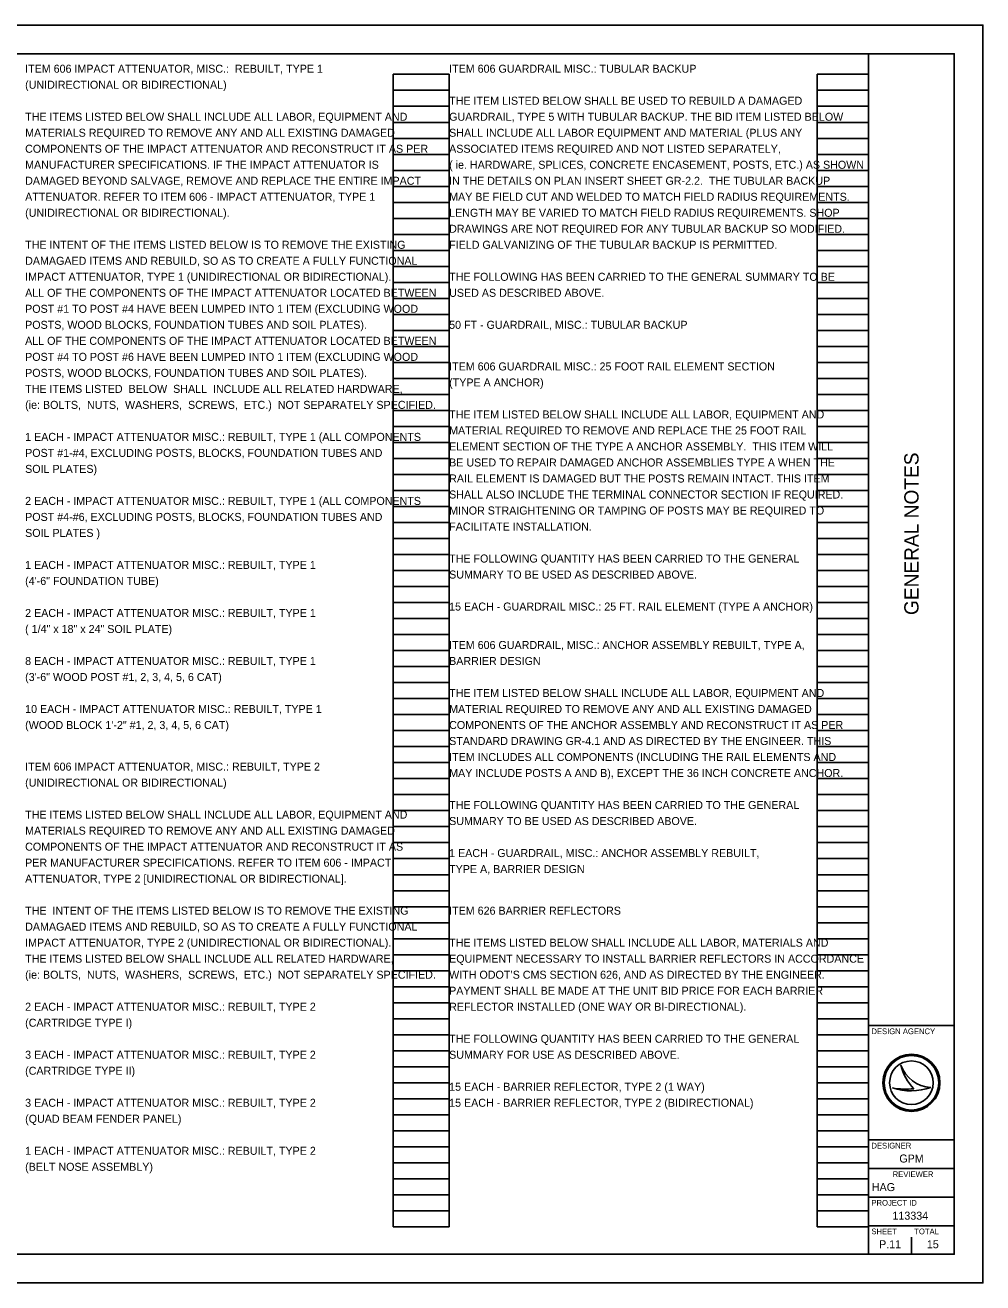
# Model space of a CAD drawing. Extents: x 0 to 34, y 0 to 22.
# Drawn here: x 17.24 to 34, y 0 to 22 of the extents above; entities that cross this region are included whole.
import ezdxf

# ---------------------------------------------------------------- set-up
doc = ezdxf.new("R2010")
doc.units = 0
for name, color, linetype in [('SH_Border', 7, 'Continuous'), ('SH_Cut_Line', 7, 'Continuous'), ('SH_Data', 7, 'Continuous'), ('SH_Text', 7, 'Continuous')]:
    doc.layers.add(name, color=color, linetype=linetype)

msp = doc.modelspace()

# ---------------------------------------------------------------- linework, layer by layer
at = {"layer": 'SH_Border'}
for p, q in [((32, 0.5), (32, 21.5)), ((32, 4.5), (33.5, 4.5)), ((32, 2.5), (33.5, 2.5)), ((32, 2), (33.5, 2)), ((32, 1.5), (33.5, 1.5)), ((32, 1), (33.5, 1))]:
    msp.add_line(p, q, dxfattribs=at)
msp.add_lwpolyline([(1.5, 21.5), (33.5, 21.5), (33.5, 0.5), (1.5, 0.5)], close=True, dxfattribs=at)
at = {"layer": 'SH_Cut_Line'}
msp.add_lwpolyline([(0, 0), (34, 0), (34, 22), (0, 22)], close=True, dxfattribs=at)
at = {"layer": 'SH_Data'}
for p, q in [((23.68, 0.98), (23.68, 21.14)), ((23.68, 21.14), (24.66, 21.14)), ((24.66, 0.98), (24.66, 21.14)), ((31.1, 0.98), (31.1, 21.14)), ((31.1, 21.14), (32, 21.14)), ((32, 0.98), (32, 21.14)), ((23.68, 20.86), (24.66, 20.86)), ((31.1, 20.86), (32, 20.86)), ((23.68, 20.58), (24.66, 20.58)), ((31.1, 20.58), (32, 20.58)), ((23.68, 20.3), (24.66, 20.3)), ((31.1, 20.3), (32, 20.3)), ((23.68, 20.02), (24.66, 20.02)), ((31.1, 20.02), (32, 20.02)), ((23.68, 19.74), (24.66, 19.74)), ((31.1, 19.74), (32, 19.74)), ((23.68, 19.46), (24.66, 19.46)), ((31.1, 19.46), (32, 19.46)), ((23.68, 19.18), (24.66, 19.18)), ((31.1, 19.18), (32, 19.18)), ((23.68, 18.9), (24.66, 18.9)), ((31.1, 18.9), (32, 18.9)), ((23.68, 18.62), (24.66, 18.62)), ((31.1, 18.62), (32, 18.62)), ((23.68, 18.34), (24.66, 18.34)), ((31.1, 18.34), (32, 18.34)), ((23.68, 18.06), (24.66, 18.06)), ((31.1, 18.06), (32, 18.06)), ((23.68, 17.78), (24.66, 17.78)), ((31.1, 17.78), (32, 17.78)), ((23.68, 17.5), (24.66, 17.5)), ((31.1, 17.5), (32, 17.5)), ((23.68, 17.22), (24.66, 17.22)), ((31.1, 17.22), (32, 17.22)), ((23.68, 16.94), (24.66, 16.94)), ((31.1, 16.94), (32, 16.94)), ((23.68, 16.66), (24.66, 16.66)), ((31.1, 16.66), (32, 16.66)), ((23.68, 16.38), (24.66, 16.38)), ((31.1, 16.38), (32, 16.38)), ((23.68, 16.1), (24.66, 16.1)), ((31.1, 16.1), (32, 16.1)), ((23.68, 15.82), (24.66, 15.82)), ((31.1, 15.82), (32, 15.82)), ((23.68, 15.54), (24.66, 15.54)), ((31.1, 15.54), (32, 15.54)), ((23.68, 15.26), (24.66, 15.26)), ((31.1, 15.26), (32, 15.26)), ((23.68, 14.98), (24.66, 14.98)), ((31.1, 14.98), (32, 14.98)), ((23.68, 14.7), (24.66, 14.7)), ((31.1, 14.7), (32, 14.7)), ((23.68, 14.42), (24.66, 14.42)), ((31.1, 14.42), (32, 14.42)), ((23.68, 14.14), (24.66, 14.14)), ((31.1, 14.14), (32, 14.14)), ((23.68, 13.86), (24.66, 13.86)), ((31.1, 13.86), (32, 13.86)), ((23.68, 13.58), (24.66, 13.58)), ((31.1, 13.58), (32, 13.58)), ((23.68, 13.3), (24.66, 13.3)), ((31.1, 13.3), (32, 13.3)), ((23.68, 13.02), (24.66, 13.02)), ((31.1, 13.02), (32, 13.02)), ((23.68, 12.74), (24.66, 12.74)), ((31.1, 12.74), (32, 12.74)), ((23.68, 12.46), (24.66, 12.46)), ((31.1, 12.46), (32, 12.46)), ((23.68, 12.18), (24.66, 12.18)), ((31.1, 12.18), (32, 12.18)), ((23.68, 11.9), (24.66, 11.9)), ((31.1, 11.9), (32, 11.9)), ((23.68, 11.62), (24.66, 11.62)), ((31.1, 11.62), (32, 11.62)), ((23.68, 11.34), (24.66, 11.34)), ((31.1, 11.34), (32, 11.34)), ((23.68, 11.06), (24.66, 11.06)), ((31.1, 11.06), (32, 11.06)), ((23.68, 10.78), (24.66, 10.78)), ((31.1, 10.78), (32, 10.78)), ((23.68, 10.5), (24.66, 10.5)), ((31.1, 10.5), (32, 10.5)), ((23.68, 10.22), (24.66, 10.22)), ((31.1, 10.22), (32, 10.22)), ((23.68, 9.94), (24.66, 9.94)), ((31.1, 9.94), (32, 9.94)), ((23.68, 9.66), (24.66, 9.66)), ((31.1, 9.66), (32, 9.66)), ((23.68, 9.38), (24.66, 9.38)), ((31.1, 9.38), (32, 9.38)), ((23.68, 9.1), (24.66, 9.1)), ((31.1, 9.1), (32, 9.1)), ((23.68, 8.82), (24.66, 8.82)), ((31.1, 8.82), (32, 8.82)), ((23.68, 8.54), (24.66, 8.54)), ((31.1, 8.54), (32, 8.54)), ((23.68, 8.26), (24.66, 8.26)), ((31.1, 8.26), (32, 8.26)), ((23.68, 7.98), (24.66, 7.98)), ((31.1, 7.98), (32, 7.98)), ((23.68, 7.7), (24.66, 7.7)), ((31.1, 7.7), (32, 7.7)), ((23.68, 7.42), (24.66, 7.42)), ((31.1, 7.42), (32, 7.42)), ((23.68, 7.14), (24.66, 7.14)), ((31.1, 7.14), (32, 7.14)), ((23.68, 6.86), (24.66, 6.86)), ((31.1, 6.86), (32, 6.86)), ((23.68, 6.58), (24.66, 6.58)), ((31.1, 6.58), (32, 6.58)), ((23.68, 6.3), (24.66, 6.3)), ((31.1, 6.3), (32, 6.3)), ((23.68, 6.02), (24.66, 6.02)), ((31.1, 6.02), (32, 6.02)), ((23.68, 5.74), (24.66, 5.74)), ((31.1, 5.74), (32, 5.74)), ((23.68, 5.46), (24.66, 5.46)), ((31.1, 5.46), (32, 5.46)), ((23.68, 5.18), (24.66, 5.18)), ((31.1, 5.18), (32, 5.18)), ((23.68, 4.9), (24.66, 4.9)), ((31.1, 4.9), (32, 4.9)), ((23.68, 4.62), (24.66, 4.62)), ((31.1, 4.62), (32, 4.62)), ((23.68, 4.34), (24.66, 4.34)), ((31.1, 4.34), (32, 4.34)), ((23.68, 4.06), (24.66, 4.06)), ((31.1, 4.06), (32, 4.06)), ((23.68, 3.78), (24.66, 3.78)), ((31.1, 3.78), (32, 3.78)), ((32.567, 3.81), (32.567, 3.81)), ((23.68, 3.5), (24.66, 3.5)), ((31.1, 3.5), (32, 3.5)), ((32.417, 3.41), (32.417, 3.41)), ((32.75, 3.5), (32.75, 3.5)), ((33.087, 3.419), (33.087, 3.419)), ((23.68, 3.22), (24.66, 3.22)), ((31.1, 3.22), (32, 3.22)), ((23.68, 2.94), (24.66, 2.94)), ((31.1, 2.94), (32, 2.94)), ((23.68, 2.66), (24.66, 2.66)), ((31.1, 2.66), (32, 2.66)), ((23.68, 2.38), (24.66, 2.38)), ((31.1, 2.38), (32, 2.38)), ((23.68, 2.1), (24.66, 2.1)), ((31.1, 2.1), (32, 2.1)), ((23.68, 1.82), (24.66, 1.82)), ((31.1, 1.82), (32, 1.82)), ((23.68, 1.54), (24.66, 1.54)), ((31.1, 1.54), (32, 1.54)), ((23.68, 1.26), (24.66, 1.26)), ((31.1, 1.26), (32, 1.26)), ((23.68, 0.98), (24.66, 0.98)), ((31.1, 0.98), (32, 0.98)), ((32.375, 0.675), (32.375, 0.675)), ((32.75, 0.5), (32.75, 0.8))]:
    msp.add_line(p, q, dxfattribs=at)
for radius in [0.5, 0.477, 0.477, 0.382]:
    msp.add_circle((32.75, 3.5), radius, dxfattribs=at)
for centre, radius, start, end in [((33.116, 3.998), 0.58, 198.9257, 198.9319), ((33.347, 3.97), 0.796, 191.6379, 191.6421), ((33.116, 3.998), 0.58, 198.9319, 267.1657), ((33.347, 3.97), 0.796, 191.6421, 226.0947), ((32.739, 4.37), 1.013, 251.4576, 290.0832), ((32.648, 4.654), 1.266, 259.4964, 259.4995), ((32.739, 4.37), 1.013, 251.4527, 251.4576), ((32.648, 4.654), 1.266, 259.4995, 276.6672)]:
    msp.add_arc(centre, radius, start, end, dxfattribs=at)

# ---------------------------------------------------------------- texts
msp.add_text('GENERAL NOTES', height=0.25, rotation=90, dxfattribs=at).set_placement((32.875, 11.682))
for s, height, p in [('DESIGN AGENCY', 0.1, (32.05, 4.35)), ('DESIGNER', 0.1, (32.05, 2.35)), ('GPM', 0.14, (32.538, 2.105)), ('REVIEWER', 0.1, (32.422, 1.85)), ('HAG', 0.14, (32.057, 1.605)), ('PROJECT ID', 0.1, (32.05, 1.35)), ('113334', 0.14, (32.418, 1.105)), ('SHEET', 0.1, (32.05, 0.85)), ('TOTAL', 0.1, (32.8, 0.85)), ('P.11', 0.14, (32.184, 0.605)), ('15', 0.14, (33.02, 0.605))]:
    msp.add_text(s, height=height, dxfattribs=at).set_placement(p)
at = {"layer": 'SH_Text'}
for s, p in [('ITEM 606 IMPACT ATTENUATOR, MISC.:  REBUILT, TYPE 1', (17.24, 21.168)), ('ITEM 606 GUARDRAIL MISC.: TUBULAR BACKUP', (24.66, 21.168)), ('(UNIDIRECTIONAL OR BIDIRECTIONAL)', (17.24, 20.888)), ('THE ITEM LISTED BELOW SHALL BE USED TO REBUILD A DAMAGED', (24.66, 20.608)), ('THE ITEMS LISTED BELOW SHALL INCLUDE ALL LABOR, EQUIPMENT AND', (17.24, 20.328)), ('GUARDRAIL, TYPE 5 WITH TUBULAR BACKUP. THE BID ITEM LISTED BELOW', (24.66, 20.328)), ('MATERIALS REQUIRED TO REMOVE ANY AND ALL EXISTING DAMAGED', (17.24, 20.048)), ('SHALL INCLUDE ALL LABOR EQUIPMENT AND MATERIAL (PLUS ANY', (24.66, 20.048)), ('COMPONENTS OF THE IMPACT ATTENUATOR AND RECONSTRUCT IT AS PER', (17.24, 19.768)), ('ASSOCIATED ITEMS REQUIRED AND NOT LISTED SEPARATELY,', (24.66, 19.768)), ('MANUFACTURER SPECIFICATIONS. IF THE IMPACT ATTENUATOR IS', (17.24, 19.488)), ('( ie. HARDWARE, SPLICES, CONCRETE ENCASEMENT, POSTS, ETC.) AS SHOWN', (24.66, 19.488)), ('DAMAGED BEYOND SALVAGE, REMOVE AND REPLACE THE ENTIRE IMPACT', (17.24, 19.208)), ('IN THE DETAILS ON PLAN INSERT SHEET GR-2.2.  THE TUBULAR BACKUP', (24.66, 19.208)), ('ATTENUATOR. REFER TO ITEM 606 - IMPACT ATTENUATOR, TYPE 1', (17.24, 18.928)), ('MAY BE FIELD CUT AND WELDED TO MATCH FIELD RADIUS REQUIREMENTS.', (24.66, 18.928)), ('(UNIDIRECTIONAL OR BIDIRECTIONAL).', (17.24, 18.648)), ('LENGTH MAY BE VARIED TO MATCH FIELD RADIUS REQUIREMENTS. SHOP', (24.66, 18.648)), ('DRAWINGS ARE NOT REQUIRED FOR ANY TUBULAR BACKUP SO MODIFIED.', (24.66, 18.368)), ('THE INTENT OF THE ITEMS LISTED BELOW IS TO REMOVE THE EXISTING', (17.24, 18.088)), ('FIELD GALVANIZING OF THE TUBULAR BACKUP IS PERMITTED. ', (24.66, 18.088)), ('DAMAGAED ITEMS AND REBUILD, SO AS TO CREATE A FULLY FUNCTIONAL', (17.24, 17.808)), ('IMPACT ATTENUATOR, TYPE 1 (UNIDIRECTIONAL OR BIDIRECTIONAL).', (17.24, 17.528)), ('THE FOLLOWING HAS BEEN CARRIED TO THE GENERAL SUMMARY TO BE', (24.66, 17.528)), ('ALL OF THE COMPONENTS OF THE IMPACT ATTENUATOR LOCATED BETWEEN', (17.24, 17.248)), ('USED AS DESCRIBED ABOVE.', (24.66, 17.248)), ('POST #1 TO POST #4 HAVE BEEN LUMPED INTO 1 ITEM (EXCLUDING WOOD', (17.24, 16.968)), ('POSTS, WOOD BLOCKS, FOUNDATION TUBES AND SOIL PLATES).', (17.24, 16.688)), ('50 FT - GUARDRAIL, MISC.: TUBULAR BACKUP ', (24.66, 16.688)), ('ALL OF THE COMPONENTS OF THE IMPACT ATTENUATOR LOCATED BETWEEN', (17.24, 16.408)), ('POST #4 TO POST #6 HAVE BEEN LUMPED INTO 1 ITEM (EXCLUDING WOOD', (17.24, 16.128)), ('ITEM 606 GUARDRAIL MISC.: 25 FOOT RAIL ELEMENT SECTION', (24.66, 15.96)), ('POSTS, WOOD BLOCKS, FOUNDATION TUBES AND SOIL PLATES).', (17.24, 15.848)), ('THE ITEMS LISTED  BELOW  SHALL  INCLUDE ALL RELATED HARDWARE,', (17.24, 15.568)), ('(TYPE A ANCHOR)', (24.66, 15.68)), ('(ie: BOLTS,  NUTS,  WASHERS,  SCREWS,  ETC.)  NOT SEPARATELY SPECIFIED.  ', (17.24, 15.288)), ('THE ITEM LISTED BELOW SHALL INCLUDE ALL LABOR, EQUIPMENT AND', (24.66, 15.12)), ('MATERIAL REQUIRED TO REMOVE AND REPLACE THE 25 FOOT RAIL', (24.66, 14.84)), ('1 EACH - IMPACT ATTENUATOR MISC.: REBUILT, TYPE 1 (ALL COMPONENTS', (17.24, 14.728)), ('POST #1-#4, EXCLUDING POSTS, BLOCKS, FOUNDATION TUBES AND', (17.24, 14.448)), ('ELEMENT SECTION OF THE TYPE A ANCHOR ASSEMBLY.  THIS ITEM WILL', (24.66, 14.56)), ('SOIL PLATES)', (17.24, 14.168)), ('BE USED TO REPAIR DAMAGED ANCHOR ASSEMBLIES TYPE A WHEN THE', (24.66, 14.28)), ('RAIL ELEMENT IS DAMAGED BUT THE POSTS REMAIN INTACT. THIS ITEM', (24.66, 14)), ('SHALL ALSO INCLUDE THE TERMINAL CONNECTOR SECTION IF REQUIRED.', (24.66, 13.72)), ('2 EACH - IMPACT ATTENUATOR MISC.: REBUILT, TYPE 1 (ALL COMPONENTS', (17.24, 13.608)), ('POST #4-#6, EXCLUDING POSTS, BLOCKS, FOUNDATION TUBES AND', (17.24, 13.328)), ('MINOR STRAIGHTENING OR TAMPING OF POSTS MAY BE REQUIRED TO', (24.66, 13.44)), ('FACILITATE INSTALLATION.  ', (24.66, 13.16)), ('SOIL PLATES )', (17.24, 13.048)), ('1 EACH - IMPACT ATTENUATOR MISC.: REBUILT, TYPE 1', (17.24, 12.488)), ('THE FOLLOWING QUANTITY HAS BEEN CARRIED TO THE GENERAL', (24.66, 12.6)), ('(4\'-6" FOUNDATION TUBE)', (17.24, 12.208)), ('SUMMARY TO BE USED AS DESCRIBED ABOVE.   ', (24.66, 12.32)), ('15 EACH - GUARDRAIL MISC.: 25 FT. RAIL ELEMENT (TYPE A ANCHOR) ', (24.66, 11.76)), ('2 EACH - IMPACT ATTENUATOR MISC.: REBUILT, TYPE 1', (17.24, 11.648)), ('( 1/4" x 18" x 24" SOIL PLATE)', (17.24, 11.368)), ('ITEM 606 GUARDRAIL, MISC.: ANCHOR ASSEMBLY REBUILT, TYPE A,', (24.66, 11.088)), ('8 EACH - IMPACT ATTENUATOR MISC.: REBUILT, TYPE 1', (17.24, 10.808)), ('BARRIER DESIGN', (24.66, 10.808)), ('(3\'-6" WOOD POST #1, 2, 3, 4, 5, 6 CAT)', (17.24, 10.528)), ('THE ITEM LISTED BELOW SHALL INCLUDE ALL LABOR, EQUIPMENT AND', (24.66, 10.248)), ('10 EACH - IMPACT ATTENUATOR MISC.: REBUILT, TYPE 1', (17.24, 9.968)), ('MATERIAL REQUIRED TO REMOVE ANY AND ALL EXISTING DAMAGED', (24.66, 9.968)), ('(WOOD BLOCK 1\'-2" #1, 2, 3, 4, 5, 6 CAT)', (17.24, 9.688)), ('COMPONENTS OF THE ANCHOR ASSEMBLY AND RECONSTRUCT IT AS PER', (24.66, 9.688)), ('STANDARD DRAWING GR-4.1 AND AS DIRECTED BY THE ENGINEER. THIS', (24.66, 9.408)), ('ITEM INCLUDES ALL COMPONENTS (INCLUDING THE RAIL ELEMENTS AND', (24.66, 9.128)), ('ITEM 606 IMPACT ATTENUATOR, MISC.: REBUILT, TYPE 2', (17.24, 8.96)), ('(UNIDIRECTIONAL OR BIDIRECTIONAL)', (17.24, 8.68)), ('MAY INCLUDE POSTS A AND B), EXCEPT THE 36 INCH CONCRETE ANCHOR.  ', (24.66, 8.848)), ('THE FOLLOWING QUANTITY HAS BEEN CARRIED TO THE GENERAL', (24.66, 8.288)), ('THE ITEMS LISTED BELOW SHALL INCLUDE ALL LABOR, EQUIPMENT AND', (17.24, 8.12)), ('SUMMARY TO BE USED AS DESCRIBED ABOVE.   ', (24.66, 8.008)), ('MATERIALS REQUIRED TO REMOVE ANY AND ALL EXISTING DAMAGED', (17.24, 7.84)), ('COMPONENTS OF THE IMPACT ATTENUATOR AND RECONSTRUCT IT AS', (17.24, 7.56)), ('1 EACH - GUARDRAIL, MISC.: ANCHOR ASSEMBLY REBUILT,', (24.66, 7.448)), ('PER MANUFACTURER SPECIFICATIONS. REFER TO ITEM 606 - IMPACT', (17.24, 7.28)), ('TYPE A, BARRIER DESIGN ', (24.66, 7.168)), ('ATTENUATOR, TYPE 2 [UNIDIRECTIONAL OR BIDIRECTIONAL].', (17.24, 7)), ('THE  INTENT OF THE ITEMS LISTED BELOW IS TO REMOVE THE EXISTING', (17.24, 6.44)), ('ITEM 626 BARRIER REFLECTORS', (24.66, 6.44)), ('DAMAGAED ITEMS AND REBUILD, SO AS TO CREATE A FULLY FUNCTIONAL', (17.24, 6.16)), ('IMPACT ATTENUATOR, TYPE 2 (UNIDIRECTIONAL OR BIDIRECTIONAL).', (17.24, 5.88)), ('THE ITEMS LISTED BELOW SHALL INCLUDE ALL LABOR, MATERIALS AND', (24.66, 5.88)), ('THE ITEMS LISTED BELOW SHALL INCLUDE ALL RELATED HARDWARE,', (17.24, 5.6)), ('EQUIPMENT NECESSARY TO INSTALL BARRIER REFLECTORS IN ACCORDANCE', (24.66, 5.6)), ('(ie: BOLTS,  NUTS,  WASHERS,  SCREWS,  ETC.)  NOT SEPARATELY SPECIFIED.', (17.24, 5.32)), ('WITH ODOT’S CMS SECTION 626, AND AS DIRECTED BY THE ENGINEER.', (24.66, 5.32)), ('PAYMENT SHALL BE MADE AT THE UNIT BID PRICE FOR EACH BARRIER', (24.66, 5.04)), ('2 EACH - IMPACT ATTENUATOR MISC.: REBUILT, TYPE 2 ', (17.24, 4.76)), ('REFLECTOR INSTALLED (ONE WAY OR BI-DIRECTIONAL).  ', (24.66, 4.76)), ('(CARTRIDGE TYPE I)', (17.24, 4.48)), ('THE FOLLOWING QUANTITY HAS BEEN CARRIED TO THE GENERAL', (24.66, 4.2)), ('3 EACH - IMPACT ATTENUATOR MISC.: REBUILT, TYPE 2', (17.24, 3.92)), ('SUMMARY FOR USE AS DESCRIBED ABOVE.  ', (24.66, 3.92)), ('(CARTRIDGE TYPE II)', (17.24, 3.64)), ('15 EACH - BARRIER REFLECTOR, TYPE 2 (1 WAY)', (24.66, 3.36)), ('3 EACH - IMPACT ATTENUATOR MISC.: REBUILT, TYPE 2', (17.24, 3.08)), ('15 EACH - BARRIER REFLECTOR, TYPE 2 (BIDIRECTIONAL)', (24.66, 3.08)), ('(QUAD BEAM FENDER PANEL)', (17.24, 2.8)), ('1 EACH - IMPACT ATTENUATOR MISC.: REBUILT, TYPE 2', (17.24, 2.24)), ('(BELT NOSE ASSEMBLY)', (17.24, 1.96))]:
    msp.add_text(s, height=0.14, dxfattribs=at).set_placement(p)

doc.saveas('drawing.dxf')
